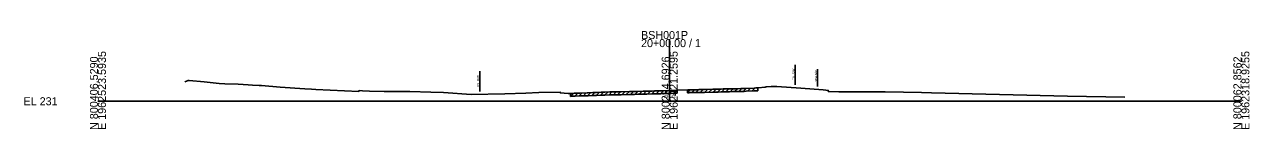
# Model space of a CAD drawing. Extents: x -26 to 1403, y -10 to 19587.
# Drawn here: x -25.7 to 402.8, y 3990.3 to 4024.5 of the extents above; entities that cross this region are included whole.
import ezdxf

# ---------------------------------------------------------------- set-up
doc = ezdxf.new("R2010")
doc.units = 0
for name, color, linetype in [('Default', 7, 'Continuous'), ('RD_GPK_XS_Cell', 7, 'Continuous'), ('RD_XS_ExGround', 7, 'Continuous'), ('RD_XS_ExPaveRet', 7, 'Continuous'), ('RD_XS_ExRW', 7, 'Continuous'), ('RD_XS_NewRW', 7, 'Continuous'), ('RD_XS_TX_Elev_EX', 7, 'Continuous')]:
    doc.layers.add(name, color=color, linetype=linetype)

msp = doc.modelspace()

# ---------------------------------------------------------------- linework, layer by layer
at = {"layer": 'RD_GPK_XS_Cell'}
for p, q in [((200, 4000), (200, 4021.65)), ((0, 4000), (200, 4000)), ((200, 4000), (400, 4000))]:
    msp.add_line(p, q, dxfattribs=at)
at = {"layer": 'RD_XS_ExGround'}
msp.add_lwpolyline([(30.44, 4006.72), (31.52, 4007.22), (31.9, 4007.2), (37.15, 4006.74), (42.42, 4006.22), (44.44, 4006.11), (49.07, 4005.9), (52.52, 4005.71), (54.04, 4005.62), (56.35, 4005.48), (57.17, 4005.43), (63.8, 4004.93), (72.43, 4004.28), (74.76, 4004.16), (76.21, 4004.08), (91.24, 4003.45), (91.35, 4003.7), (92.6, 4003.66), (95.02, 4003.54), (100.18, 4003.38), (109.14, 4003.35), (116.4, 4003.14), (120.91, 4003.04), (130.51, 4002.36), (142.37, 4002.64), (149.65, 4002.82), (154.25, 4003.01), (161.72, 4003.13), (161.78, 4002.88), (163.07, 4002.81), (164.55, 4002.71), (165.3, 4002.66), (165.97, 4002.72), (166.59, 4002.79), (166.94, 4002.8), (168.56, 4002.85), (171.11, 4002.93), (171.48, 4002.94), (173.18, 4003.02), (174.38, 4003.06), (176.05, 4003.12), (176.83, 4003.16), (177.29, 4003.17), (179.08, 4003.25), (180.19, 4003.25), (180.9, 4003.25), (182.28, 4003.27), (183.09, 4003.28), (185.98, 4003.34), (187.74, 4003.4), (188.89, 4003.44), (190.68, 4003.49), (191.37, 4003.51), (192.02, 4003.52), (193.92, 4003.56), (194.71, 4003.57), (195.03, 4003.58), (195.55, 4003.6), (196.86, 4003.64), (197.65, 4003.65), (200, 4003.72), (200.54, 4003.73), (201.66, 4003.78), (202.28, 4003.81), (206.32, 4003.96), (206.71, 4003.98), (207, 4003.99), (207.46, 4003.99), (209.3, 4004.02), (209.64, 4004.03), (210.21, 4004.04), (212.21, 4004.08), (215.12, 4004.16), (216.93, 4004.22), (218.02, 4004.25), (218.76, 4004.28), (220.03, 4004.3), (220.59, 4004.31), (220.91, 4004.32), (222.23, 4004.35), (223.81, 4004.38), (224.86, 4004.41), (226.03, 4004.45), (226.72, 4004.48), (229.55, 4004.59), (230.1, 4004.62), (230.95, 4004.63), (233.37, 4004.93), (233.75, 4004.98), (235.46, 4005.19), (236.27, 4005.17), (237.52, 4005.12), (245.85, 4004.6), (253.66, 4003.96), (254.64, 4003.86), (255.46, 4003.79), (255.56, 4003.34), (259.19, 4003.32), (273.27, 4003.26), (274.48, 4003.26), (275.42, 4003.26), (281.83, 4003.15), (288.05, 4003.01), (291.55, 4002.92), (339.17, 4001.73), (359.21, 4001.38)], dxfattribs=at)
at = {"layer": 'RD_XS_ExPaveRet'}
for p, q in [((165.3, 4001.66), (166.42, 4002.77)), ((165.3, 4001.66), (165.3, 4002.66)), ((166.8, 4001.8), (167.84, 4002.83)), ((168.3, 4001.85), (169.34, 4002.88)), ((169.8, 4001.89), (170.84, 4002.92)), ((171.3, 4001.94), (172.35, 4002.98)), ((172.8, 4002.01), (173.84, 4003.04)), ((174.3, 4002.06), (175.34, 4003.1)), ((175.8, 4002.11), (176.85, 4003.16)), ((177.3, 4002.18), (178.35, 4003.22)), ((178.8, 4002.24), (179.82, 4003.25)), ((180.3, 4002.25), (181.31, 4003.26)), ((181.8, 4002.27), (182.82, 4003.28)), ((183.3, 4002.29), (184.32, 4003.31)), ((184.8, 4002.31), (185.82, 4003.33)), ((186.3, 4002.35), (187.34, 4003.39)), ((187.8, 4002.4), (188.83, 4003.44)), ((189.3, 4002.45), (190.33, 4003.48)), ((190.68, 4002.49), (191.37, 4002.51)), ((190.8, 4002.49), (191.83, 4003.52)), ((191.37, 4002.51), (192.02, 4002.52)), ((192.02, 4002.52), (193.92, 4002.56)), ((192.3, 4002.52), (193.33, 4003.55)), ((193.8, 4002.56), (194.83, 4003.58)), ((193.92, 4002.56), (194.71, 4002.57)), ((194.71, 4002.57), (195.03, 4002.58)), ((195.03, 4002.58), (195.55, 4002.6)), ((195.3, 4002.59), (196.34, 4003.62)), ((195.55, 4002.6), (196.86, 4002.64)), ((196.8, 4002.64), (197.83, 4003.66)), ((196.86, 4002.64), (197.65, 4002.65)), ((197.65, 4002.65), (200, 4002.72)), ((198.3, 4002.67), (199.33, 4003.7)), ((199.8, 4002.71), (200.84, 4003.74)), ((200, 4002.72), (200.54, 4002.73)), ((200.54, 4002.73), (201.66, 4002.78)), ((201.3, 4002.76), (202.36, 4003.82)), ((201.66, 4002.78), (202.28, 4002.81)), ((202.28, 4002.81), (202.65, 4002.83)), ((202.65, 4003.83), (202.65, 4002.83)), ((206.2, 4002.96), (207.23, 4003.99)), ((206.2, 4002.96), (206.2, 4003.96)), ((206.2, 4002.96), (206.32, 4002.96)), ((206.32, 4002.96), (206.71, 4002.98)), ((206.71, 4002.98), (207, 4002.99)), ((207, 4002.99), (207.46, 4002.99)), ((207.46, 4002.99), (209.3, 4003.02)), ((207.7, 4003), (208.72, 4004.01)), ((209.2, 4003.02), (210.22, 4004.04)), ((209.3, 4003.02), (209.64, 4003.03)), ((209.64, 4003.03), (210.21, 4003.04)), ((210.21, 4003.04), (212.21, 4003.08)), ((210.7, 4003.05), (211.72, 4004.07)), ((212.2, 4003.08), (213.23, 4004.11)), ((212.21, 4003.08), (215.12, 4003.16)), ((213.7, 4003.12), (214.73, 4004.15)), ((215.12, 4003.16), (216.93, 4003.22)), ((215.2, 4003.17), (216.23, 4004.2)), ((216.7, 4003.21), (217.73, 4004.24)), ((216.93, 4003.22), (218.02, 4003.25)), ((218.02, 4003.25), (218.76, 4003.28)), ((218.2, 4003.26), (219.23, 4004.28)), ((218.76, 4003.28), (220.03, 4003.3)), ((219.7, 4003.29), (220.72, 4004.31)), ((220.03, 4003.3), (220.59, 4003.31)), ((220.59, 4003.31), (220.91, 4003.32)), ((220.91, 4003.32), (222.23, 4003.35)), ((221.2, 4003.32), (222.22, 4004.35)), ((222.23, 4003.35), (223.81, 4003.38)), ((222.7, 4003.36), (223.72, 4004.38)), ((223.81, 4003.38), (224.86, 4003.41)), ((224.2, 4003.39), (225.23, 4004.43)), ((224.86, 4003.41), (226.03, 4003.45)), ((225.7, 4003.44), (226.74, 4004.48)), ((226.03, 4003.45), (226.72, 4003.48)), ((226.72, 4003.48), (229.55, 4003.59)), ((227.2, 4003.5), (228.24, 4004.54)), ((228.7, 4003.56), (229.74, 4004.6)), ((229.55, 4003.59), (230.1, 4003.62)), ((230.1, 4003.62), (230.81, 4003.63)), ((230.81, 4004.63), (230.81, 4003.63)), ((165.3, 4001.66), (165.97, 4001.72)), ((165.97, 4001.72), (166.59, 4001.79)), ((166.59, 4001.79), (166.94, 4001.8)), ((166.94, 4001.8), (168.56, 4001.85)), ((168.56, 4001.85), (171.11, 4001.93)), ((171.11, 4001.93), (171.48, 4001.94)), ((171.48, 4001.94), (173.18, 4002.02)), ((173.18, 4002.02), (174.38, 4002.06)), ((174.38, 4002.06), (176.05, 4002.12)), ((176.05, 4002.12), (176.83, 4002.16)), ((176.83, 4002.16), (177.29, 4002.17)), ((177.29, 4002.17), (179.08, 4002.25)), ((179.08, 4002.25), (180.19, 4002.25)), ((180.19, 4002.25), (180.9, 4002.25)), ((180.9, 4002.25), (182.28, 4002.27)), ((182.28, 4002.27), (183.09, 4002.28)), ((183.09, 4002.28), (185.98, 4002.34)), ((185.98, 4002.34), (187.74, 4002.4)), ((187.74, 4002.4), (188.89, 4002.44)), ((188.89, 4002.44), (190.68, 4002.49))]:
    msp.add_line(p, q, dxfattribs=at)
at = {"layer": 'RD_XS_ExRW'}
for p, q in [((243.91, 4005.72), (243.91, 4012.72)), ((133.62, 4003.43), (133.62, 4010.43))]:
    msp.add_line(p, q, dxfattribs=at)
at = {"layer": 'RD_XS_NewRW'}
msp.add_line((251.7, 4011.16), (251.7, 4005.16), dxfattribs=at)

# ---------------------------------------------------------------- texts
at = {"layer": 'Default'}
msp.add_text('-', height=0.0001, dxfattribs=at).set_placement((0, 4000))
at = {"layer": 'RD_GPK_XS_Cell'}
for s, p in [('BSH001P', (190, 4021.65)), ('20+00.00 / 1', (190, 4018.85)), ('EL 231', (-26, 3998.6))]:
    msp.add_text(s, height=2.8, dxfattribs=at).set_placement(p)
for s, p in [('N 800406.5290', (0, 3990)), ('E 1962523.5935', (2.8, 3990)), ('N 800234.6926', (200, 3990)), ('E 1962421.2595', (202.8, 3990)), ('N 800062.8562', (400, 3990)), ('E 1962318.9255', (402.8, 3990))]:
    msp.add_text(s, height=2.8, rotation=90, dxfattribs=at).set_placement(p)
at = {"layer": 'RD_XS_ExRW'}
for p in [(243.66, 4007.39), (133.37, 4005.1)]:
    msp.add_text('EX. R/W ', height=0.75, rotation=90, dxfattribs=at).set_placement(p)
at = {"layer": 'RD_XS_NewRW'}
msp.add_text('NEW R/W ', height=0.65, rotation=90, dxfattribs=at).set_placement((251.44, 4006.72))
at = {"layer": 'RD_XS_TX_Elev_EX'}
msp.add_text('234.72', height=1, dxfattribs=at).set_placement((197.96, 4001.22))

doc.saveas('drawing.dxf')
